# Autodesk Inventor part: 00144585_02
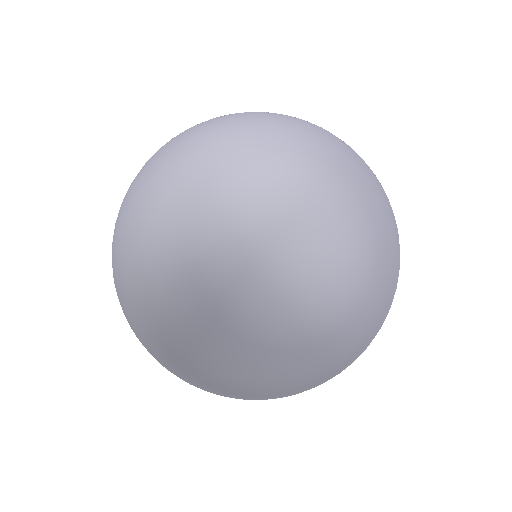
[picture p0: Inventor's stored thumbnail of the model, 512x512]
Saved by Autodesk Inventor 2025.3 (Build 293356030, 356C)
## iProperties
Created: 2021-02
Part Number: 00144585_02
Material: Generico
Document SubType Name: Modeling
Designer: R5800u
Density: 1 g/cm^3
Appearance: Default
Author: TraceParts
Sending System: SolidWorks 2021
Last Author: Albert
Last Saved: 2021-07-28
IsFastener: 1
TYPE: CATASM
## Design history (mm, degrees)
feature "Imported1"
node "Solido1"
